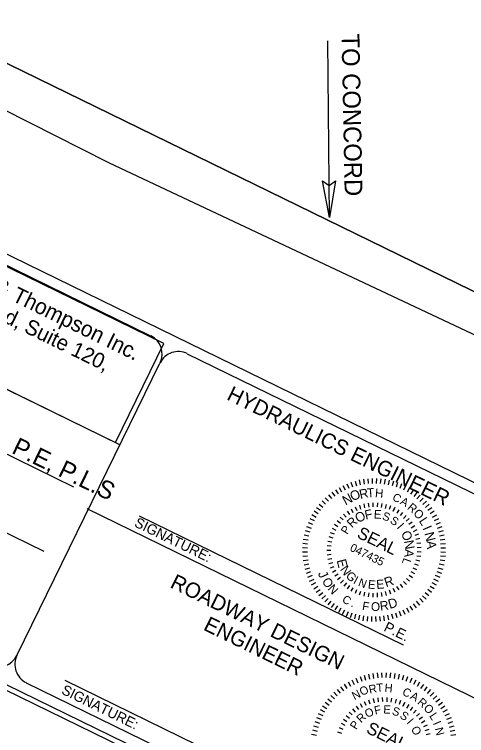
# Model space of a CAD drawing. Extents: x 1517888 to 1526099, y 633375 to 640181.
# Drawn here: x 1520197 to 1520641, y 637084 to 637793 of the extents above; entities that cross this region are included whole.
import ezdxf

# ---------------------------------------------------------------- set-up
doc = ezdxf.new("R2010")
doc.units = 0
for name, color, linetype in [('Default', 7, 'Continuous'), ('Prop Terminator CELL', 7, 'Continuous'), ('Scratch_Level_0', 7, 'Continuous'), ('Sheet Clip Boundary CELL', 7, 'Continuous'), ('Sheet Data Field CELL', 7, 'Continuous'), ('Sheet Plot Border Inside CELL', 7, 'Continuous'), ('Sheet Title CELL', 7, 'Continuous')]:
    doc.layers.add(name, color=color, linetype=linetype)

msp = doc.modelspace()

# ---------------------------------------------------------------- linework, layer by layer
at = {"layer": 'Default'}
for p, q in [((1520527.58, 637333.33), (1520529.13, 637328.8)), ((1520531.63, 637334.59), (1520532.91, 637329.97)), ((1520535.77, 637335.59), (1520536.76, 637330.91)), ((1520539.94, 637336.35), (1520540.65, 637331.61)), ((1520544.16, 637336.85), (1520544.58, 637332.08)), ((1520548.4, 637337.1), (1520548.53, 637332.3)), ((1520552.65, 637337.08), (1520552.49, 637332.29)), ((1520556.89, 637336.82), (1520556.44, 637332.04)), ((1520561.1, 637336.3), (1520560.36, 637331.55)), ((1520565.28, 637335.52), (1520564.26, 637330.84)), ((1520569.4, 637334.49), (1520568.1, 637329.88)), ((1520573.45, 637333.21), (1520571.87, 637328.69)), ((1520512.32, 637325.96), (1520514.91, 637321.92)), ((1520515.96, 637328.15), (1520518.3, 637323.97)), ((1520519.72, 637330.11), (1520521.81, 637325.8)), ((1520523.6, 637331.84), (1520525.42, 637327.41)), ((1520577.41, 637331.7), (1520575.57, 637327.28)), ((1520581.29, 637329.94), (1520579.18, 637325.64)), ((1520585.04, 637327.96), (1520582.68, 637323.79)), ((1520588.67, 637325.75), (1520586.06, 637321.73)), ((1520505.47, 637320.94), (1520508.53, 637317.26)), ((1520508.81, 637323.55), (1520511.65, 637319.68)), ((1520592.16, 637323.33), (1520589.31, 637319.48)), ((1520595.49, 637320.71), (1520592.42, 637317.03)), ((1520496.44, 637311.97), (1520500.12, 637308.9)), ((1520499.26, 637315.15), (1520502.75, 637311.85)), ((1520502.27, 637318.14), (1520505.55, 637314.63)), ((1520540.18, 637312.03), (1520541.06, 637308.12)), ((1520544.59, 637312.8), (1520545.09, 637308.83)), ((1520549.06, 637313.13), (1520549.17, 637309.14)), ((1520553.54, 637313.04), (1520553.26, 637309.06)), ((1520557.99, 637312.52), (1520557.32, 637308.57)), ((1520562.36, 637311.56), (1520561.32, 637307.71)), ((1520598.67, 637317.88), (1520595.37, 637314.39)), ((1520601.66, 637314.87), (1520598.16, 637311.59)), ((1520604.47, 637311.68), (1520600.78, 637308.62)), ((1520491.39, 637305.14), (1520495.41, 637302.53)), ((1520493.81, 637308.63), (1520497.66, 637305.79)), ((1520523.89, 637304.86), (1520526.16, 637301.58)), ((1520527.68, 637307.24), (1520529.63, 637303.75)), ((1520531.69, 637309.23), (1520533.29, 637305.58)), ((1520535.87, 637310.83), (1520537.12, 637307.03)), ((1520566.62, 637310.19), (1520565.22, 637306.46)), ((1520570.73, 637308.42), (1520568.98, 637304.83)), ((1520568.98, 637304.83), (1520570.73, 637308.42)), ((1520574.66, 637306.25), (1520572.56, 637302.86)), ((1520607.08, 637308.33), (1520603.21, 637305.5)), ((1520609.49, 637304.82), (1520605.45, 637302.24)), ((1520487.2, 637297.76), (1520491.5, 637295.65)), ((1520489.19, 637301.52), (1520493.35, 637299.15)), ((1520517.06, 637299.06), (1520519.94, 637296.29)), ((1520520.33, 637302.13), (1520522.92, 637299.08)), ((1520578.35, 637303.73), (1520575.94, 637300.54)), ((1520581.78, 637300.85), (1520579.07, 637297.91)), ((1520584.92, 637297.66), (1520581.94, 637295)), ((1520611.67, 637301.18), (1520607.49, 637298.84)), ((1520613.63, 637297.42), (1520609.32, 637295.33)), ((1520485.45, 637293.89), (1520489.87, 637292.04)), ((1520511.49, 637292.07), (1520514.83, 637289.9)), ((1520514.11, 637295.71), (1520517.23, 637293.22)), ((1520587.73, 637294.17), (1520584.52, 637291.81)), ((1520590.2, 637290.44), (1520586.77, 637288.4)), ((1520615.37, 637293.54), (1520610.94, 637291.72)), ((1520482.65, 637285.87), (1520487.26, 637284.57)), ((1520483.93, 637289.92), (1520488.45, 637288.34)), ((1520507.36, 637284.14), (1520511.06, 637282.65)), ((1520509.23, 637288.21), (1520512.77, 637286.36)), ((1520592.3, 637286.48), (1520588.68, 637284.78)), ((1520616.86, 637289.57), (1520612.33, 637288.02)), ((1520618.12, 637285.51), (1520613.5, 637284.23)), ((1520480.85, 637277.57), (1520485.59, 637276.84)), ((1520481.63, 637281.75), (1520486.31, 637280.73)), ((1520505.89, 637279.91), (1520509.71, 637278.78)), ((1520594, 637282.34), (1520590.23, 637281)), ((1520595.29, 637278.05), (1520591.42, 637277.08)), ((1520619.12, 637281.38), (1520614.44, 637280.39)), ((1520619.88, 637277.2), (1520615.14, 637276.49)), ((1520480.07, 637269.12), (1520484.85, 637268.96)), ((1520480.33, 637273.36), (1520485.1, 637272.92)), ((1520504.19, 637271.12), (1520508.17, 637270.75)), ((1520504.82, 637275.56), (1520508.74, 637274.8)), ((1520596.17, 637273.66), (1520592.22, 637273.06)), ((1520596.61, 637269.21), (1520592.63, 637268.99)), ((1520620.38, 637272.99), (1520615.6, 637272.56)), ((1520480.05, 637264.88), (1520484.84, 637265.01)), ((1520504, 637266.65), (1520507.99, 637266.67)), ((1520504.22, 637262.19), (1520508.2, 637262.58)), ((1520596.63, 637264.72), (1520592.64, 637264.9)), ((1520620.61, 637264.5), (1520615.82, 637264.66)), ((1520620.62, 637268.74), (1520615.83, 637268.61)), ((1520480.29, 637260.63), (1520485.07, 637261.06)), ((1520480.79, 637256.41), (1520485.53, 637257.12)), ((1520504.88, 637257.75), (1520508.8, 637258.53)), ((1520595.37, 637255.87), (1520591.49, 637256.81)), ((1520596.21, 637260.27), (1520592.26, 637260.84)), ((1520619.83, 637256.04), (1520615.08, 637256.78)), ((1520620.35, 637260.25), (1520615.57, 637260.7)), ((1520481.55, 637252.24), (1520486.24, 637253.23)), ((1520482.56, 637248.11), (1520487.17, 637249.38)), ((1520505.98, 637253.41), (1520509.79, 637254.56)), ((1520507.47, 637249.19), (1520511.17, 637250.71)), ((1520592.43, 637247.42), (1520588.8, 637249.09)), ((1520594.1, 637251.57), (1520590.33, 637252.89)), ((1520618.02, 637247.74), (1520613.41, 637249.05)), ((1520619.04, 637251.86), (1520614.36, 637252.89)), ((1520483.81, 637244.05), (1520488.34, 637245.6)), ((1520485.3, 637240.08), (1520489.73, 637241.9)), ((1520509.38, 637245.14), (1520512.9, 637247)), ((1520511.66, 637241.29), (1520514.99, 637243.49)), ((1520584.76, 637242.15), (1520588.01, 637239.82)), ((1520590.36, 637243.45), (1520586.91, 637245.46)), ((1520615.22, 637239.73), (1520610.8, 637241.58)), ((1520616.74, 637243.7), (1520612.22, 637245.27)), ((1520487.04, 637236.19), (1520491.35, 637238.28)), ((1520489, 637232.43), (1520493.18, 637234.77)), ((1520514.31, 637237.67), (1520517.41, 637240.18)), ((1520517.28, 637234.32), (1520520.14, 637237.13)), ((1520523.12, 637234.37), (1520520.55, 637231.3)), ((1520582.01, 637232.98), (1520579.28, 637235.89)), ((1520585.13, 637236.19), (1520582.13, 637238.83)), ((1520611.48, 637232.1), (1520607.32, 637234.46)), ((1520613.47, 637235.86), (1520609.17, 637237.97)), ((1520491.18, 637228.79), (1520495.22, 637231.38)), ((1520493.59, 637225.29), (1520497.46, 637228.12)), ((1520524.14, 637228.58), (1520526.4, 637231.88)), ((1520527.95, 637226.23), (1520529.87, 637229.73)), ((1520531.97, 637224.26), (1520533.56, 637227.92)), ((1520536.16, 637222.69), (1520537.38, 637226.49)), ((1520566.91, 637223.54), (1520565.49, 637227.26)), ((1520571.01, 637225.33), (1520569.23, 637228.91)), ((1520574.92, 637227.53), (1520572.8, 637230.91)), ((1520578.59, 637230.08), (1520576.16, 637233.25)), ((1520606.86, 637224.98), (1520603.01, 637227.83)), ((1520609.28, 637228.47), (1520605.26, 637231.08)), ((1520496.21, 637221.94), (1520499.89, 637225)), ((1520499.01, 637218.75), (1520502.51, 637222.03)), ((1520502, 637215.74), (1520505.3, 637219.23)), ((1520540.49, 637221.53), (1520541.33, 637225.43)), ((1520544.9, 637220.79), (1520545.37, 637224.76)), ((1520549.37, 637220.48), (1520549.45, 637224.48)), ((1520553.85, 637220.6), (1520553.55, 637224.59)), ((1520558.29, 637221.16), (1520557.61, 637225.09)), ((1520562.67, 637222.13), (1520561.6, 637225.99)), ((1520601.41, 637218.47), (1520597.92, 637221.77)), ((1520604.23, 637221.65), (1520600.56, 637224.72)), ((1520505.18, 637212.91), (1520508.25, 637216.59)), ((1520508.51, 637210.28), (1520511.36, 637214.14)), ((1520591.86, 637210.06), (1520589.02, 637213.93)), ((1520595.2, 637212.68), (1520592.15, 637216.36)), ((1520598.4, 637215.48), (1520595.12, 637218.98)), ((1520512, 637207.87), (1520514.61, 637211.88)), ((1520515.63, 637205.66), (1520517.99, 637209.83)), ((1520519.39, 637203.67), (1520521.49, 637207.98)), ((1520523.26, 637201.92), (1520525.1, 637206.34)), ((1520577.07, 637201.78), (1520575.25, 637206.21)), ((1520580.95, 637203.51), (1520578.86, 637207.82)), ((1520584.71, 637205.47), (1520582.37, 637209.65)), ((1520588.35, 637207.66), (1520585.77, 637211.69)), ((1520527.22, 637200.41), (1520528.8, 637204.93)), ((1520531.27, 637199.13), (1520532.57, 637203.74)), ((1520535.39, 637198.1), (1520536.41, 637202.78)), ((1520539.57, 637197.32), (1520540.31, 637202.06)), ((1520543.78, 637196.8), (1520544.23, 637201.58)), ((1520548.02, 637196.54), (1520548.18, 637201.32)), ((1520552.27, 637196.52), (1520552.14, 637201.31)), ((1520556.51, 637196.77), (1520556.09, 637201.54)), ((1520560.73, 637197.27), (1520560.02, 637202)), ((1520564.9, 637198.02), (1520563.92, 637202.71)), ((1520569.04, 637199.03), (1520567.76, 637203.65)), ((1520573.09, 637200.28), (1520571.54, 637204.81)), ((1520536.57, 637142.4), (1520538.15, 637137.79)), ((1520540.7, 637143.67), (1520542, 637138.97)), ((1520544.9, 637144.7), (1520545.91, 637139.93)), ((1520549.15, 637145.46), (1520549.87, 637140.64)), ((1520553.44, 637145.98), (1520553.87, 637141.12)), ((1520557.76, 637146.23), (1520557.89, 637141.35)), ((1520562.08, 637146.21), (1520561.91, 637141.34)), ((1520566.39, 637145.94), (1520565.94, 637141.08)), ((1520570.67, 637145.41), (1520569.92, 637140.59)), ((1520574.93, 637144.62), (1520573.88, 637139.86)), ((1520579.12, 637143.57), (1520577.79, 637138.88)), ((1520583.24, 637142.27), (1520581.63, 637137.67)), ((1520521.05, 637134.89), (1520523.68, 637130.79)), ((1520524.75, 637137.12), (1520527.13, 637132.87)), ((1520528.58, 637139.11), (1520530.7, 637134.73)), ((1520532.53, 637140.88), (1520534.38, 637136.37)), ((1520587.27, 637140.73), (1520585.39, 637136.23)), ((1520591.21, 637138.95), (1520589.06, 637134.57)), ((1520595.03, 637136.93), (1520592.63, 637132.69)), ((1520598.72, 637134.68), (1520596.07, 637130.6)), ((1520514.08, 637129.79), (1520517.19, 637126.04)), ((1520517.48, 637132.45), (1520520.36, 637128.51)), ((1520602.27, 637132.22), (1520599.37, 637128.3)), ((1520605.66, 637129.55), (1520602.54, 637125.81)), ((1520504.89, 637120.66), (1520508.63, 637117.53)), ((1520507.77, 637123.89), (1520511.32, 637120.54)), ((1520510.83, 637126.94), (1520514.16, 637123.37)), ((1520549.39, 637120.72), (1520550.28, 637116.75)), ((1520553.88, 637121.5), (1520554.38, 637117.46)), ((1520558.42, 637121.84), (1520558.53, 637117.79)), ((1520562.98, 637121.75), (1520562.7, 637117.7)), ((1520567.51, 637121.22), (1520566.83, 637117.21)), ((1520571.96, 637120.25), (1520570.9, 637116.32)), ((1520608.9, 637126.67), (1520605.54, 637123.12)), ((1520611.94, 637123.61), (1520608.38, 637120.28)), ((1520614.79, 637120.36), (1520611.04, 637117.25)), ((1520499.76, 637113.72), (1520503.84, 637111.06)), ((1520502.22, 637117.27), (1520506.14, 637114.37)), ((1520532.82, 637113.43), (1520535.13, 637110.09)), ((1520536.67, 637115.85), (1520538.65, 637112.3)), ((1520540.75, 637117.88), (1520542.38, 637114.16)), ((1520545, 637119.5), (1520546.27, 637115.64)), ((1520576.29, 637118.85), (1520574.86, 637115.05)), ((1520580.47, 637117.05), (1520578.69, 637113.4)), ((1520578.69, 637113.4), (1520580.47, 637117.05)), ((1520584.46, 637114.85), (1520582.33, 637111.39)), ((1520617.45, 637116.96), (1520613.52, 637114.08)), ((1520619.9, 637113.39), (1520615.79, 637110.76)), ((1520495.49, 637106.2), (1520499.87, 637104.06)), ((1520497.51, 637110.03), (1520501.75, 637107.62)), ((1520525.88, 637107.53), (1520528.8, 637104.71)), ((1520529.2, 637110.65), (1520531.83, 637107.55)), ((1520588.22, 637112.27), (1520585.77, 637109.03)), ((1520591.71, 637109.35), (1520588.96, 637106.36)), ((1520594.91, 637106.1), (1520591.88, 637103.39)), ((1520622.12, 637109.69), (1520617.87, 637107.31)), ((1520624.12, 637105.86), (1520619.73, 637103.74)), ((1520493.71, 637102.27), (1520498.21, 637100.39)), ((1520520.2, 637100.42), (1520523.61, 637098.21)), ((1520522.87, 637104.12), (1520526.04, 637101.58)), ((1520597.77, 637102.56), (1520594.5, 637100.16)), ((1520600.28, 637098.76), (1520596.78, 637096.68)), ((1520625.88, 637101.91), (1520621.37, 637100.06)), ((1520490.87, 637094.11), (1520495.56, 637092.79)), ((1520492.17, 637098.23), (1520496.77, 637096.63)), ((1520516, 637092.35), (1520519.76, 637090.83)), ((1520517.9, 637096.49), (1520521.5, 637094.61)), ((1520602.41, 637094.73), (1520598.73, 637093)), ((1520627.4, 637097.87), (1520622.79, 637096.29)), ((1520628.68, 637093.74), (1520623.98, 637092.44)), ((1520489.03, 637085.67), (1520493.85, 637084.92)), ((1520489.82, 637089.92), (1520494.58, 637088.88)), ((1520514.5, 637088.04), (1520518.4, 637086.9)), ((1520604.14, 637090.51), (1520600.31, 637089.15)), ((1520605.46, 637086.15), (1520601.52, 637085.17)), ((1520629.7, 637089.54), (1520624.93, 637088.53)), ((1520630.47, 637085.29), (1520625.65, 637084.57))]:
    msp.add_line(p, q, dxfattribs=at)
at = {"layer": 'Prop Terminator CELL'}
msp.add_lwpolyline([(1520512.39, 637629.54), (1520506.5, 637593.49), (1520499.79, 637629.64), (1520506.23, 637625.09)], close=True, dxfattribs=at)
at = {"layer": 'Scratch_Level_0'}
msp.add_lwpolyline([(1519830.66, 639089.56), (1521178.15, 638430.53), (1520716.83, 637487.3), (1519369.35, 638146.33)], close=True, dxfattribs=at)
at = {"layer": 'Sheet Clip Boundary CELL'}
msp.add_lwpolyline([(1519997.22, 638878.25), (1520677.94, 638519.75), (1521000.39, 638385.3), (1521102.69, 638308.65), (1521171.04, 638278.93), (1521395.99, 638165.98), (1521492.2, 638121.51), (1521760.41, 637993.13), (1521455.66, 637316.28), (1521359.72, 637143.34), (1520289.98, 637647.3), (1519534.36, 638030.12)], close=True, dxfattribs=at)
at = {"layer": 'Sheet Data Field CELL'}
msp.add_line((1520506.5, 637593.49), (1520505.02, 637767.11), dxfattribs=at)
at = {"layer": 'Sheet Plot Border Inside CELL'}
msp.add_lwpolyline([(1517931.1, 638233.43), (1520925.19, 636769.09), (1521852.3, 638664.72), (1518858.21, 640129.06)], close=True, dxfattribs=at)
at = {"layer": 'Sheet Title CELL'}
for p, q in [((1518493.77, 638386.96), (1521044.99, 637139.22)), ((1519818.88, 637727.75), (1520330.92, 637477.32)), ((1520300.77, 637370.14), (1519752.81, 637638.17)), ((1519976.47, 637465.23), (1520255.21, 637328.88)), ((1520366.85, 637459.74), (1520725.77, 637284.21)), ((1520199.5, 637163.08), (1520340.09, 637450.54)), ((1519945.25, 637403), (1520225.98, 637265.7)), ((1520268.21, 637307.67), (1520664.67, 637113.77)), ((1520319.61, 637300.31), (1520578.78, 637173.55)), ((1520246.75, 637138.78), (1520500.96, 637014.42))]:
    msp.add_line(p, q, dxfattribs=at)
for points in [[(1519395.98, 638200.78), (1519369.35, 638146.33), (1520716.83, 637487.3)], [(1518227.99, 638093.91), (1520887.01, 636793.44)], [(1520208.69, 637136.35), (1520567.61, 636960.81)]]:
    msp.add_lwpolyline(points, dxfattribs=at)
msp.add_lwpolyline([(1519757.24, 637635.98), (1520296.33, 637372.33), (1520343.91, 637469.61), (1519804.82, 637733.27)], close=True, dxfattribs=at)
for centre, start, end in [((1520322.18, 637459.43), 333.93772, 63.93772), ((1520358.11, 637441.85), 63.93772, 153.93772), ((1520181.59, 637171.97), 243.93772, 333.93772), ((1520217.52, 637154.39), 153.93772, 243.93772)]:
    msp.add_arc(centre, 20, start, end, dxfattribs=at)

# ---------------------------------------------------------------- texts
at = {"layer": 'Default'}
for s, height, rotation, p in [('O', 9.34, 25.602, (1520529.33, 637314.49)), ('R', 9.14, 12.54527, (1520536.89, 637316.77)), ('T', 8.85, 4.38431, (1520543.68, 637318.42)), ('H', 8.46, 354.95236, (1520550.98, 637318.71)), ('N', 9.33, 27.56144, (1520522.25, 637310.45)), ('C', 7.99, 331.24167, (1520567.5, 637316.32)), ('A', 7.99, 331.24167, (1520575.26, 637312.34)), ('R', 8.23, 319.23237, (1520582.33, 637307.56)), ('O', 9.33, 27.42157, (1520534.52, 637293.11)), ('F', 9.13, 12.12532, (1520542.12, 637296.55)), ('E', 8.54, 356.82908, (1520549.84, 637297.79)), ('O', 8.34, 316.17555, (1520588.27, 637302.09)), ('R', 8.84, 42.71781, (1520528.53, 637288.06)), ('S', 8.05, 341.53283, (1520557.78, 637296.96)), ('S', 8.05, 326.23659, (1520565.23, 637294.04)), ('L', 8.86, 303.03927, (1520593.99, 637295.33)), ('P', 8.08, 58.01406, (1520523.96, 637281.49)), ('I', 8.54, 310.94034, (1520572.09, 637288.76)), ('I', 9.2, 293.4638, (1520597.73, 637288.33)), ('SEAL', 11.981, 333.88471, (1520532.64, 637279.49)), ('O', 9.13, 295.64409, (1520576.5, 637283.14)), ('N', 9.34, 284.16934, (1520599.67, 637283.2)), ('N', 9.33, 280.34785, (1520579.67, 637275.63)), ('047435', 7.981, 333.88471, (1520525.9, 637266.44)), ('A', 9.22, 274.4018, (1520601.8, 637275.59)), ('A', 8.84, 265.0516, (1520580.72, 637267.84)), ('E', 9.34, 283.9548, (1520513.49, 637256.64)), ('L', 8.07, 249.75535, (1520579.57, 637259.6)), ('N', 8.79, 304.80987, (1520516.58, 637247.71)), ('J', 9.17, 294.53429, (1520494.95, 637243.68)), ('G', 8.44, 313.5761, (1520521.95, 637240.91)), ('I', 7.99, 331.6709, (1520529.36, 637234.44)), ('R', 9.29, 18.4496, (1520562.1, 637230.07)), ('O', 8.86, 303.20687, (1520498.72, 637236.11)), ('N', 8.49, 312.17935, (1520504.23, 637228.35)), ('N', 8.02, 339.30056, (1520534.11, 637231.81)), ('E', 8.45, 354.69263, (1520543.97, 637228.96)), ('E', 8.86, 4.67851, (1520552.82, 637228.42)), ('C', 8, 329.97466, (1520518.19, 637216.1)), ('D', 9.26, 17.20913, (1520565.74, 637208.78)), ('.', 8, 337.71701, (1520527, 637211.54)), ('F', 8.29, 350.50133, (1520538.2, 637208.02)), ('O', 8.65, 359.50389, (1520547.24, 637206.85)), ('R', 9, 8.3265, (1520556.6, 637207.1)), ('R', 8.12, 12.54527, (1520546.05, 637125.54)), ('T', 8.12, 4.38431, (1520552.95, 637127.22)), ('H', 8.12, 354.95236, (1520560.38, 637127.52)), ('N', 8.12, 27.56144, (1520531.15, 637119.12)), ('O', 8.12, 25.602, (1520538.36, 637123.22)), ('C', 8.12, 331.24167, (1520577.18, 637125.09)), ('A', 8.12, 331.24167, (1520585.08, 637121.04)), ('R', 8.12, 319.23237, (1520592.28, 637116.18)), ('F', 8.12, 12.12532, (1520551.37, 637104.98)), ('E', 8.12, 356.82908, (1520559.22, 637106.24)), ('O', 8.12, 316.17555, (1520598.31, 637110.62)), ('R', 8.12, 42.71781, (1520537.54, 637096.34)), ('O', 8.12, 27.42157, (1520543.64, 637101.47)), ('S', 8.12, 341.53283, (1520567.3, 637105.39)), ('S', 8.12, 326.23659, (1520574.88, 637102.43)), ('L', 8.12, 303.03927, (1520604.14, 637103.73)), ('P', 8.12, 58.01406, (1520532.89, 637089.65)), ('I', 8.12, 310.94034, (1520581.86, 637097.05)), ('I', 8.12, 293.4638, (1520607.94, 637096.62)), ('SEAL', 12.189, 333.88471, (1520541.72, 637087.61)), ('O', 8.12, 295.64409, (1520586.34, 637091.33)), ('N', 8.12, 284.16934, (1520609.91, 637091.39))]:
    msp.add_text(s, height=height, rotation=rotation, dxfattribs=at).set_placement(p)
at = {"layer": 'Sheet Data Field CELL'}
for s, height, rotation, p in [('TO CONCORD', 17.5, 271.1075, (1520518.41, 637774.18)), ('REECE M. SCHULER, P.E, P.L.S', 17.5002, 333.93772, (1519973.77, 637469.81))]:
    msp.add_text(s, height=height, rotation=rotation, dxfattribs=at).set_placement(p)
at = {"layer": 'Sheet Title CELL'}
for s, height, p in [('Johnson, Mirmiran, & Thompson Inc.', 15.3336, (1520014.65, 637599.77)), ('2550 West Tyvola Road, Suite 120,', 14.8955, (1520004.76, 637579.56)), (' HYDRAULICS ENGINEER', 15, (1520399.66, 637417.51)), ('SIGNATURE:', 9.999, (1520314.12, 637290.33)), ('ROADWAY DESIGN', 14.9988, (1520349.08, 637230.33)), ('ENGINEER', 14.999, (1520381.82, 637188.71)), ('P.E.', 9.999, (1520559.09, 637187.74)), ('SIGNATURE:', 9.999, (1520242.48, 637125.95))]:
    msp.add_text(s, height=height, rotation=333.93772, dxfattribs=at).set_placement(p)

doc.saveas('drawing.dxf')
